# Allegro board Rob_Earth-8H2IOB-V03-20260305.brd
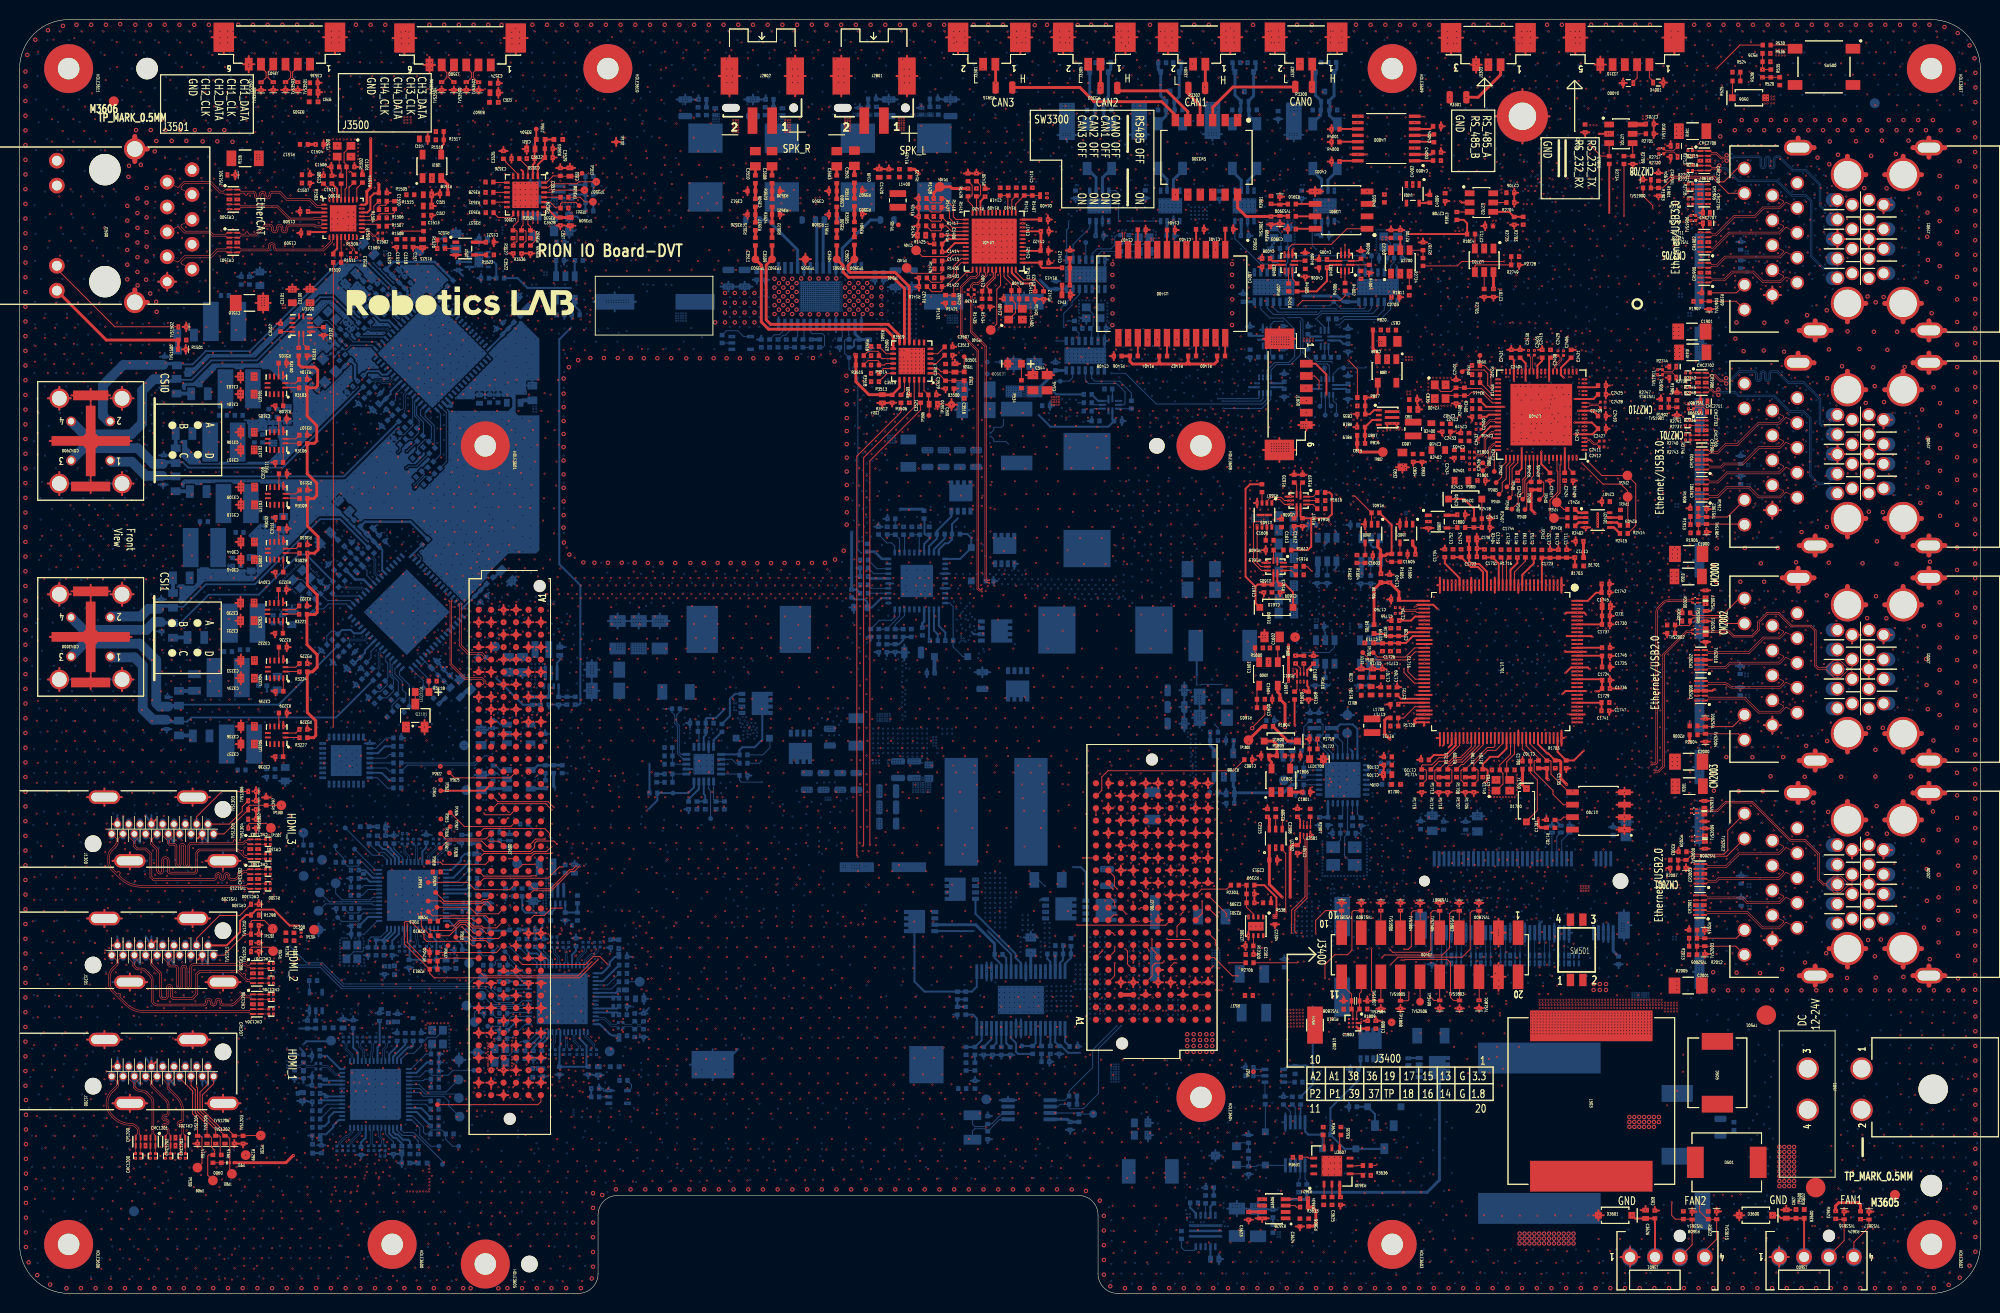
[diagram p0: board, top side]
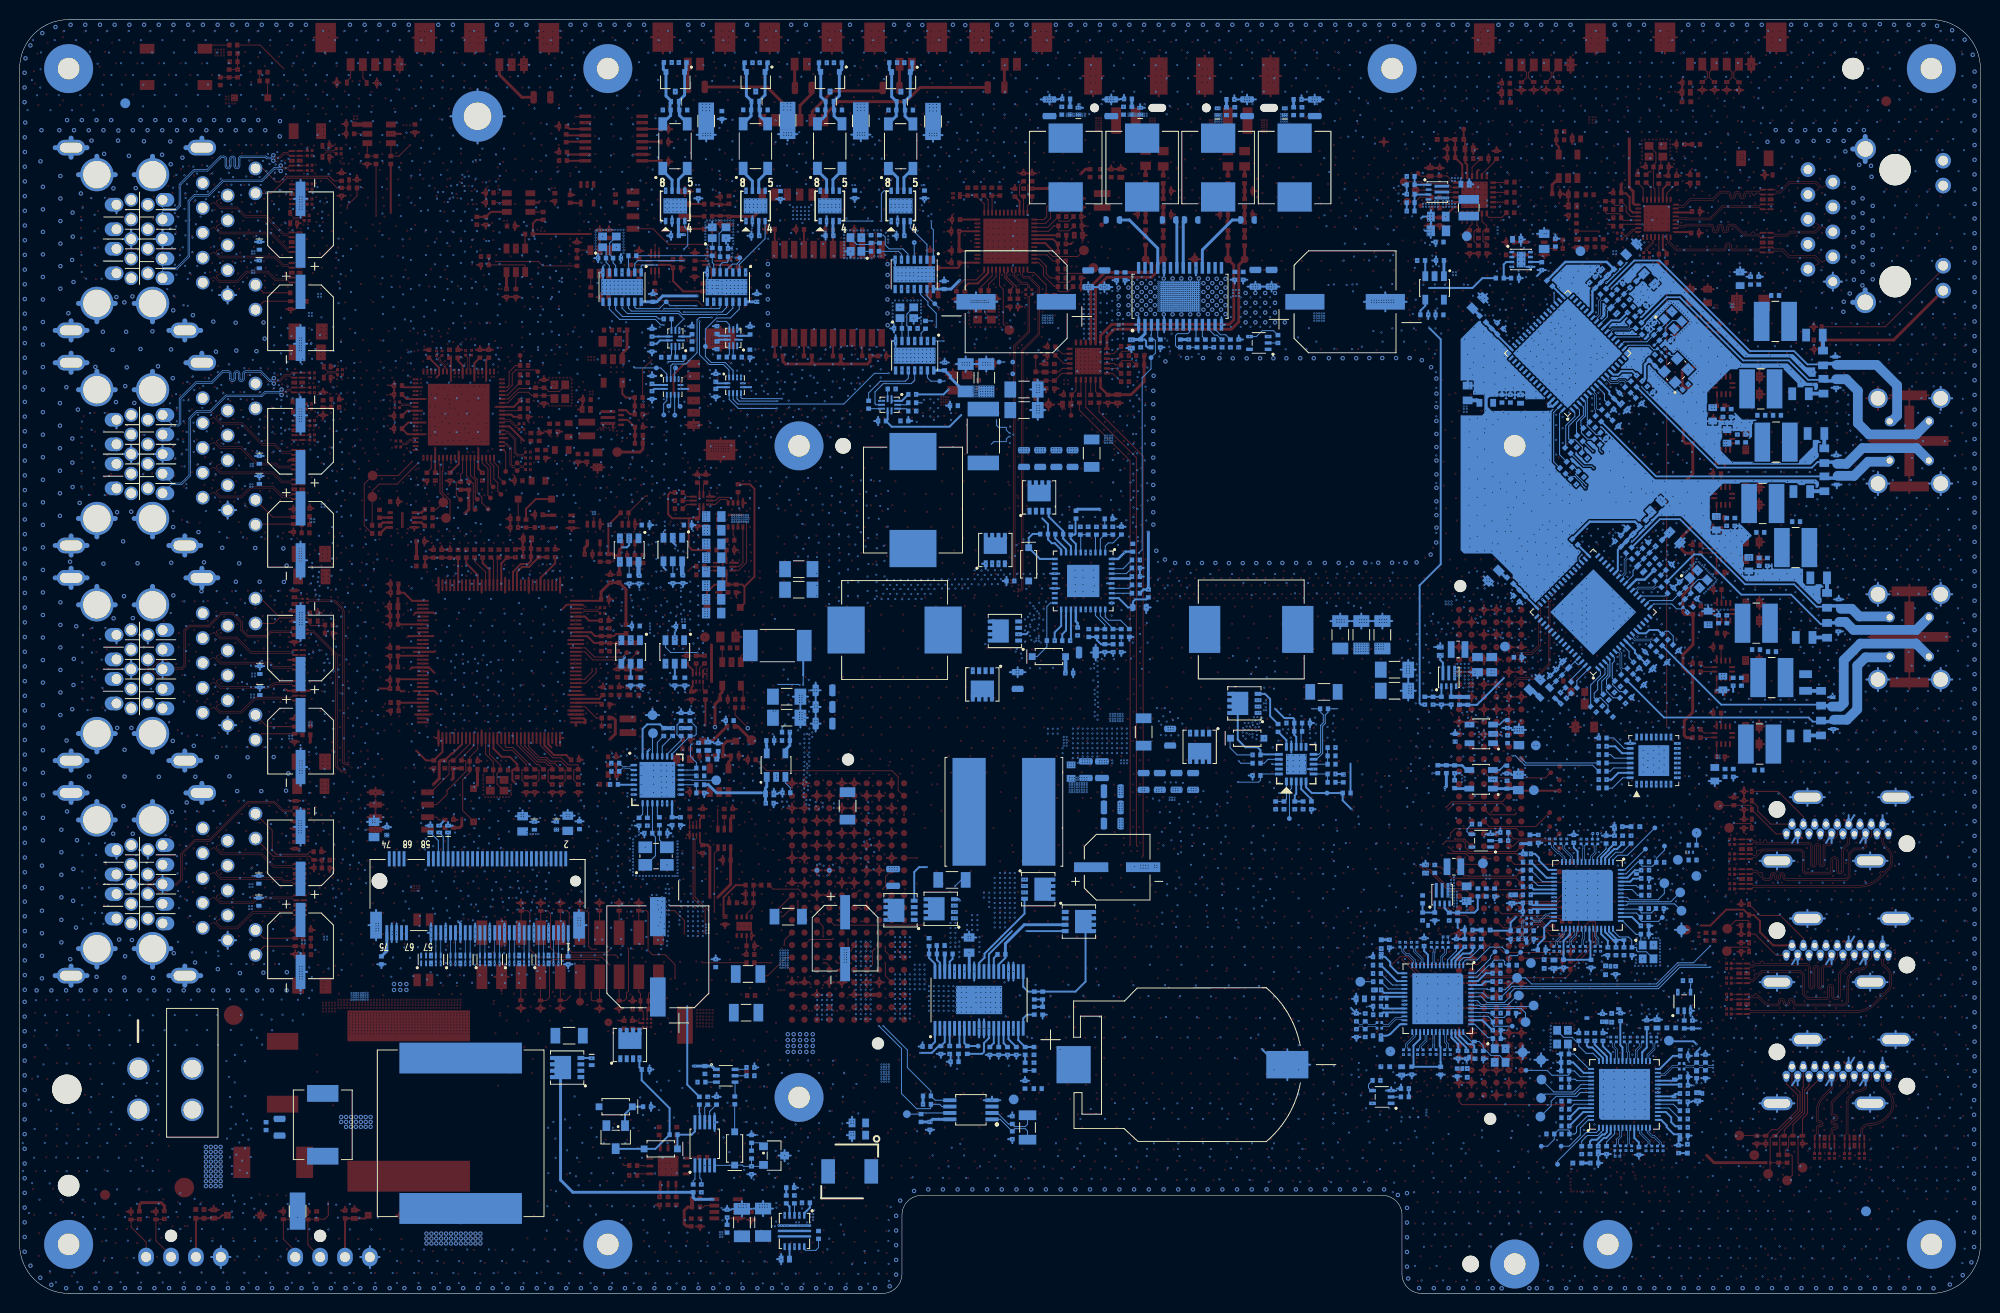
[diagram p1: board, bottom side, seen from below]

Outline 200 x 130 mm; copper layers: TOP, L2, L3, L4, L5, L6, L7, BOTTOM. Coordinates in mm from the lower left corner of the outline.
Outline path: 0,125 arc(1.46,128.54) 5,130 195,130 arc(198.54,128.54) 200,125 200,5 arc(198.54,1.46) 195,0 112,0 arc(110.59,0.59) 110,2 110,8 arc(109.41,9.41) 108,10 61,10 arc(59.59,9.41) 59,8 59,2 arc(58.41,0.59) 57,0 5,0 arc(1.46,1.46) 0,5 0,125

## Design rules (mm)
constraint set DEFAULT: min track width 0.1, pair gap 0.1
net group 8211_1_SGMII_CLK_: nets 8211_1_SGMII_CLK_M 8211_1_SGMII_CLK_P
net group CAN_MCLK1: nets CAN_MCLK1 N33124752
net group CAN_MCLK2: nets CAN_MCLK2 N33124961
net group CHANNEL1_IN: nets CHANNEL1_INM CHANNEL1_INP
net group CHANNEL2_IN: nets CHANNEL2_INM CHANNEL2_INP
net group CHANNEL3_IN: nets CHANNEL3_INM CHANNEL3_INP
net group CHANNEL4_IN: nets CHANNEL4_INM CHANNEL4_INP
net group DES0_SIOA_: nets DES0_SIOA_M DES0_SIOA_P
net group DES0_SIOB_: nets DES0_SIOB_M DES0_SIOB_P
net group DES0_SIOC_: nets DES0_SIOC_M DES0_SIOC_P
net group DES0_SIOD_: nets DES0_SIOD_M DES0_SIOD_P
net group DES1_SIOA_: nets DES1_SIOA_M DES1_SIOA_P
net group DES1_SIOB_: nets DES1_SIOB_M DES1_SIOB_P
net group DES1_SIOC_: nets DES1_SIOC_M DES1_SIOC_P
net group DES1_SIOD_: nets DES1_SIOD_M DES1_SIOD_P
net group DIFFPAIR10: nets PCIE1_TX0_M PCIE1_TX0_P
net group DIFFPAIR11: nets PCIE1_RX0_M PCIE1_RX0_P
net group DIFFPAIR14: nets PCIE1_REFCLK_M PCIE1_REFCLK_P
net group DP1: nets USB2_HUB_DM4 USB2_HUB_DP4
net group DP3: nets PCIE1_TX1_M PCIE1_TX1_P
net group DP4: nets PCIE1_RX1_M PCIE1_RX1_P
net group DP5: nets PCIE1_TX2_M PCIE1_TX2_P
net group DP6: nets PCIE1_RX2_M PCIE1_RX2_P
net group DP7: nets PCIE1_TX3_M PCIE1_TX3_P
net group DP8: nets PCIE1_RX3_M PCIE1_RX3_P
net group DP9: nets N30751825 N30751859
net group DP10: nets N30751883 N30751917
net group DP11: nets N30751975 N30752009
net group DP12: nets N30752033 N30752067
net group DP13: nets N30751690 N30751718
net group DP14: nets HSIN_C HSIP_C
net group DP16: nets N30797296 N30797329
net group DP22: nets N29328245 N29328252
net group DP23: nets N29318624 N29318651
net group DP25: nets N29318885 N29318891
net group DP26: nets N29318627 N29318675
net group DP28: nets N30797353 N30797387
net group DP29: nets HUB_USB2_DM_CON HUB_USB2_DP_CON
net group DP37: nets HUB_USB1_DM_CON HUB_USB1_DP_CON
net group DP40: nets HUB_USB3_DM_CON HUB_USB3_DP_CON
net group DP43: nets HUB_USB4_DM_CON HUB_USB4_DP_CON
net group DP44: nets HUB_USB3_RX_M HUB_USB3_RX_P
net group DP45: nets N30797440 N30797473
net group DP46: nets N30797491 N30797525
net group DP47: nets HUB_USB4_TX_M HUB_USB4_TX_P
net group DP48: nets HUB_USB4_RX_M HUB_USB4_RX_P
net group DP49: nets N30793801 N30793834
net group DP50: nets N30793858 N30793892
net group DP51: nets N30793945 N30793978
net group DP52: nets N30793996 N30794030
net group DP53: nets N30797523 N30797553
net group DP54: nets N30564853 N30564873
net group DP57: nets N30797438 N30797471
net group DP58: nets N30797385 N30797405
net group DP59: nets N30797294 N30797327
net group DP60: nets N30797137 N30797160
net group DP61: nets N30794028 N30794058
net group DP62: nets N30793943 N30793976
net group DP63: nets N30793890 N30793910
net group DP64: nets N30793799 N30793832
net group DP65: nets N30751823 N30751857
net group DP66: nets N30751915 N30751941
net group DP67: nets N30751973 N30752007
net group DP68: nets N30752065 N30752096
net group DP74: nets N31105694 N31105696
net group DP76: nets N30852150 N30852169
net group DP77: nets N30793642 N30793665
net group HSO_C: nets HSON_C HSOP_C
net group HUB_P2_USB_HS_: nets USB1_HS_D_M USB1_HS_D_P
net group HUB_USB1_D: nets HUB_USB1_DM HUB_USB1_DP
net group HUB_USB1_RX_: nets HUB_USB1_RX_M HUB_USB1_RX_P
net group HUB_USB1_TX_: nets HUB_USB1_TX_M HUB_USB1_TX_P
net group HUB_USB2_D: nets HUB_USB2_DM HUB_USB2_DP
net group HUB_USB2_RX_: nets HUB_USB2_RX_M HUB_USB2_RX_P
net group HUB_USB2_TX_: nets HUB_USB2_TX_M HUB_USB2_TX_P
net group HUB_USB3_D: nets HUB_USB3_DM HUB_USB3_DP
net group HUB_USB3_TX_: nets HUB_USB3_TX_M HUB_USB3_TX_P
net group HUB_USB4_D: nets HUB_USB4_DM HUB_USB4_DP
net group HUBPCIE14_REFCLK: nets HUBPCIE14_REFCLKN HUBPCIE14_REFCLKP
net group HUBPCIE14_RX_: nets HUBPCIE14_RX_N HUBPCIE14_RX_P
net group HUBPCIE14_TX_: nets HUBPCIE14_TX_N HUBPCIE14_TX_P
net group P1_MDI: nets P1_MDI_AN P1_MDI_AP
net group P1_MDI_B: nets P1_MDI_BN P1_MDI_BP
net group P1_MDI_C: nets P1_MDI_CN P1_MDI_CP
net group P1_MDI_D: nets P1_MDI_DN P1_MDI_DP
net group P2_MDI: nets P2_MDI_AN P2_MDI_AP
net group P2_MDI_B: nets P2_MDI_BN P2_MDI_BP
net group P2_MDI_C: nets P2_MDI_CN P2_MDI_CP
net group P2_MDI_D: nets P2_MDI_DN P2_MDI_DP
net group SAIL_CAN_0_: nets SAIL_CAN_0_M SAIL_CAN_0_P
net group SAIL_CAN_1_: nets SAIL_CAN_1_M SAIL_CAN_1_P
net group SGMII1_RX_: nets SGMII1_RX_M SGMII1_RX_P
net group SGMII1_TX_: nets SGMII1_TX_M SGMII1_TX_P
net group SSRX0: nets SSRX0+ SSRX0-
net group SSTX0: nets SSTX0+ SSTX0-
net group SSTX1: nets SSTX1+ SSTX1-
net group SSTX2: nets SSTX2+ SSTX2-
net group SSTX3: nets SSTX3+ SSTX3-
net group SSTX4: nets SSTX4+ SSTX4-
net group USB1_SS_RX_: nets USB1_SS_RX_M USB1_SS_RX_P
net group USB1_SS_TX_: nets USB1_SS_TX_M USB1_SS_TX_P
net group USB2_HS_D_: nets USB2_HUB_DM1 USB2_HUB_DP1
net group USB2_HUB2_D1: nets USB2_HUB2_DM1 USB2_HUB2_DP1
net group USB2_HUB2_D2: nets USB2_HUB2_DM2 USB2_HUB2_DP2
net group USB2_HUB2_D3: nets USB2_HUB2_DM3 USB2_HUB2_DP3
net group USB2_HUB2_D4: nets USB2_HUB2_DM4 USB2_HUB2_DP4
net group USBDP0: nets USBDP0+ USBDP0-
net group 8211: nets 8211_TRXN0 8211_TRXN1 8211_TRXN2 8211_TRXN3 8211_TRXP0 8211_TRXP1 8211_TRXP2 8211_TRXP3
net group CSI0: nets CSI0_A0_CLK_M CSI0_A1_LN1_P CSI0_A2_LN2_M CSI0_B0_LN0_P CSI0_B1_LN1_M CSI0_B2_LN3_P CSI0_C0_LN0_M CSI0_C1_LN2_P CSI0_C2_LN3_M CSI0_NC_CLK_P
net group CSI1: nets CSI1_A0_CLK_M CSI1_A1_LN1_P CSI1_A2_LN2_M CSI1_B0_LN0_P CSI1_B1_LN1_M CSI1_B2_LN3_P CSI1_C0_LN0_M CSI1_C1_LN2_P CSI1_C2_LN3_M CSI1_NC_CLK_P
net group EDP1: nets EDP1_AUX_M EDP1_AUX_P EDP1_LN0_M EDP1_LN0_P EDP1_LN1_M EDP1_LN1_P EDP1_LN2_M EDP1_LN2_P EDP1_LN3_M EDP1_LN3_P
net group EDP2: nets EDP2_AUX_M EDP2_AUX_P EDP2_LN0_M EDP2_LN0_P EDP2_LN1_M EDP2_LN1_P EDP2_LN2_M EDP2_LN2_P EDP2_LN3_M EDP2_LN3_P
net group EDP3: nets EDP3_AUX_M EDP3_AUX_P EDP3_LN0_M EDP3_LN0_P EDP3_LN1_M EDP3_LN1_P EDP3_LN2_M EDP3_LN2_P EDP3_LN3_M EDP3_LN3_P
net group HDIM1: nets HDMI1_CLK_N HDMI1_CLK_P HDMI1_TX0_N HDMI1_TX0_P HDMI1_TX1_N HDMI1_TX1_P HDMI1_TX2_N HDMI1_TX2_P
net group HDIM3: nets HDMI3_CLK_N_CONN HDMI3_CLK_P_CONN HDMI3_TX0_N_CONN HDMI3_TX0_P_CONN HDMI3_TX1_P_CONN HDMI3_TX2_N_CONN HDMI3_TX2_P_CONN
net group HDMI2: nets HDMI2_CLK_N HDMI2_CLK_N_CONN HDMI2_CLK_P HDMI2_CLK_P_CONN HDMI2_TX0_N HDMI2_TX0_N_CONN HDMI2_TX0_P HDMI2_TX0_P_CONN HDMI2_TX1_N HDMI2_TX1_N_CONN HDMI2_TX1_P HDMI2_TX1_P_CONN HDMI2_TX2_N HDMI2_TX2_N_CONN HDMI2_TX2_P HDMI2_TX2_P_CONN
net group HDMI3: nets HDMI3_CLK_N HDMI3_CLK_P HDMI3_TX0_N HDMI3_TX0_P HDMI3_TX1_N HDMI3_TX1_P HDMI3_TX2_N HDMI3_TX2_P
net group HUB_USB1_CON: nets HUB_USB1_RX_M_CON HUB_USB1_RX_P_CON HUB_USB1_TX_M_CON HUB_USB1_TX_P_CON
net group HUB_USB2: nets HUB_USB2_RX_M_CON HUB_USB2_RX_P_CON HUB_USB2_TX_M_CON HUB_USB2_TX_P_CON
net group HUB_USB3_CON: nets HUB_USB3_RX_M_CON HUB_USB3_RX_P_CON HUB_USB3_TX_M_CON HUB_USB3_TX_P_CON
net group HUB_USB4: nets HUB_USB4_RX_M_CON HUB_USB4_RX_P_CON HUB_USB4_TX_M_CON HUB_USB4_TX_P_CON
net group P0MDI: nets P0MDIAN P0MDIAP P0MDIBN P0MDIBP P0MDICN P0MDICP P0MDIDN P0MDIDP
net group P3_MDI: nets P3_MDI_AN P3_MDI_AP P3_MDI_BN P3_MDI_BP P3_MDI_CN P3_MDI_CP P3_MDI_DN P3_MDI_DP
net group P4_MDI: nets P4_MDI_AN P4_MDI_AP P4_MDI_BN P4_MDI_BP P4_MDI_CN P4_MDI_CP P4_MDI_DN P4_MDI_DP
net group SGMII0: nets SGMII0_RX_M SGMII0_RX_P SGMII0_TX_M SGMII0_TX_P
nets with their own width: nets GND

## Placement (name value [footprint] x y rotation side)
B900  120R/1.3A  [FB0402H0_5]  31.53 27.1 0 bottom
B901  120R/1.3A  [FB0402H0_5]  41.12 13.3 180 bottom
B902  120R/1.3A  [FB0402H0_5]  37.61 28.13 270 bottom
B903  120R/1.3A  [FB0402H0_5]  29.88 14.77 270 bottom
B1000  120R/1.3A  [FB0402H0_5]  60.7 23.14 180 bottom
B1001  120R/1.3A  [FB0402H0_5]  50.46 37.09 0 bottom
B1002  120R/1.3A  [FB0402H0_5]  52.34 22.5 90 bottom
B1003  120R/1.3A  [FB0402H0_5]  61.12 35.64 90 bottom
B1100  120R/1.3A  [FB0402H0_5]  44.5 33.62 90 bottom
B1101  120R/1.3A  [FB0402H0_5]  35.19 47.64 0 bottom
B1102  120R/1.3A  [FB0402H0_5]  38.24 32.98 90 bottom
B1103  120R/1.3A  [FB0402H0_5]  45.95 46.35 90 bottom
B1700  120R/1.3A  [FB0402H0_5]  140.4 51.95 0 top
B1701  120R/1.3A  [FB0402H0_5]  159.08 75.1 0 top
B1702  120R/1.3A  [FB0402H0_5]  137.66 66.39 0 top
B1703  120R/1.3A  [FB0402H0_5]  159.09 74.24 0 top
B1704  120R/1.3A  [FB0402H0_5]  136.85 61.5 90 top
B1705  120R/1.3A  [FB0402H0_5]  138.15 67.8 270 top
B1706  120R/1.3A  [FB0402H0_5]  138.85 73 270 top
B2400  120R/3.0A  [FB0603H0_95]  144 88.12 90 top
B2401  120R/3.0A  [FB0603H0_95]  147.08 82.94 0 top
B2402  120R/3.0A  [FB0603H0_95]  144.7 86.07 0 top
B2500  120R/1.3A  [FB0402H0_5]  129.35 54.52 180 bottom
B2900  120R/1.3A  [FB0402H0_5]  35.41 102.97 315 bottom
B2901  120R/1.3A  [FB0402H0_5]  37.04 104.84 135 bottom
B2902  120R/3.0A  [FB0603H0_95]  50.4 90.89 0 bottom
B2903  120R/1.3A  [FB0402H0_5]  50.75 99.43 225 bottom
B3000  120R/1.3A  [FB0402H0_5]  32.8 76.56 315 bottom
B3001  120R/3.0A  [FB0603H0_95]  44.44 61.33 315 bottom
B3002  120R/1.3A  [FB0402H0_5]  34.44 78.59 135 bottom
B3003  120R/1.3A  [FB0402H0_5]  47.96 72.74 225 bottom
B3500  120R/1.3A  [FB0402H0_5]  96.35 91.8 90 top
B3501  NC 120R/1.3A  [FB0402H0_5]  96.35 93.6 90 top
B3502  120R/1.3A  [FB0402H0_5]  48.38 121.56 180 top
B3503  120R/1.3A  [FB0402H0_5]  54.95 117.77 180 top
B3504  NC 120R/1.3A  [FB0402H0_5]  53.15 117.77 180 top
B3505  120R/1.3A  [FB0402H0_5]  29.99 121.61 180 top
B3600  120R/1.3A  [FB0402H0_5]  182.03 8.11 90 top
B3602  NC 120R/1.3A  [FB0402H0_5]  181.19 8.11 90 top
C500  100nF/50V_2  [0402]  174.86 17.07 270 bottom
C501  100nF/50V_2  [0402]  129 33.7 90 bottom
C502  10uF/50V_5  [SC0805H1_45]  173.49 16.96 270 bottom
C503  470nF/16V_2  [0402]  86.14 73.16 0 bottom
C504  2.2uF/10V_2  [0402]  91.01 77.84 270 bottom
C505  2.2uF/10V_2  [0402]  92.94 63.31 0 bottom
C506  100nF/50V_2  [0402]  95.51 77.49 0 bottom
C507  2.2uF/10V_2  [0402]  98.94 72.71 180 bottom
C508  100nF/50V_2  [0402]  94.82 66.62 180 bottom
C509  100nF/16V_2  [0402]  104.7 90.6 180 bottom
C510  100uF/6.3V_6  [SC1206H1_8]  97.55 90.15 180 bottom
C511  100uF/6.3V_6  [SC1206H1_8]  97.55 92.25 180 bottom
C512  100uF/6.3V_6  [SC1206H1_8]  101.4 93.45 90 bottom
C513  100uF/6.3V_6  [SC1206H1_8]  103.5 93.45 90 bottom
C514  47uF/25V_6  [SC1206H1_8]  120.53 71.81 180 bottom
C515  47uF/25V_6  [SC1206H1_8]  120.53 73.91 180 bottom
C516  47uF/25V_6  [SC1206H1_8]  121.76 58.75 180 bottom
C517  47uF/25V_6  [SC1206H1_8]  121.76 60.9 180 bottom
C518  100nF/16V_2  [0402]  127.57 58.46 180 bottom
C519  NC 39pF/50V_2  [0402]  88.48 67.4 90 bottom
C520  100nF/16V_2  [0402]  86.81 67.4 90 bottom
C521  6.8nF/50V_2  [0402]  87.63 65.85 90 bottom
C522  220nF/50V_3  [SC0603]  85.76 70.01 0 bottom
C523  10nF/50V_2  [0402]  86.14 74.86 0 bottom
C524  22uF/10V_3  [SC0603DE-H1_1]  129.21 69.43 0 bottom
C525  22uF/10V_3  [SC0603DE-H1_1]  129.21 70.83 0 bottom
C526  22uF/10V_3  [SC0603DE-H1_1]  129.21 72.23 0 bottom
C527  22uF/10V_3  [SC0603DE-H1_1]  129.21 73.63 0 bottom
C528  10uF/50V_5  [SC0805H1_45]  91.09 65.41 180 bottom
C529  10uF/50V_5  [SC0805H1_45]  98.2 62.55 90 bottom
C530  10uF/50V_5  [SC0805H1_45]  117.95 58.15 0 bottom
C531  10uF/50V_5  [SC0805H1_45]  117.95 59.85 0 bottom
C532  10uF/50V_5  [SC0805H1_45]  117.95 61.55 0 bottom
C533  10uF/50V_5  [SC0805H1_45]  92.6 85.2 90 bottom
C534  10uF/50V_5  [SC0805H1_45]  97.55 85.2 90 bottom
C535  10uF/50V_5  [SC0805H1_45]  94.25 85.2 90 bottom
C536  10uF/50V_5  [SC0805H1_45]  95.9 85.2 90 bottom
C537  22uF/10V_3  [SC0603DE-H1_1]  129.19 75.08 0 bottom
C538  22uF/10V_3  [SC0603DE-H1_1]  129.19 76.48 0 bottom
C539  22uF/10V_3  [SC0603DE-H1_1]  129.19 77.88 0 bottom
C540  22uF/10V_3  [SC0603DE-H1_1]  129.19 79.28 0 bottom
C541  100nF/50V_2  [0402]  128.92 19.67 270 bottom
C542  100nF/50V_2  [0402]  130.47 10.72 90 bottom
C543  1uF/10V_2  [0402]  125.45 23.06 180 bottom
C544  22uF/10V_3  [SC0603DE-H1_1]  103.35 92.95 90 top
C545  22uF/10V_3  [SC0603DE-H1_1]  104.8 92.95 90 top
C546  1uF/10V_2  [0402]  130.1 22.8 270 bottom
C547  100nF/50V_2  [0402]  125.35 12.57 90 bottom
C548  2.2nF/50V_2  [0402]  136.15 22.85 180 bottom
C549  6.8pF/50V_2  [0402]  88.49 77.84 270 bottom
C550  100nF/16V_2  [0402]  87.61 77.84 270 bottom
C551  3.9nF/50V_2  [0402]  88.92 79.05 0 bottom
C608  10uF/50V_5  [SC0805H1_45]  85.35 52.25 270 bottom
C609  10uF/50V_5  [SC0805H1_45]  82.65 56.77 90 bottom
C610  10uF/50V_5  [SC0805H1_45]  80.3 52.25 270 bottom
C611  10uF/50V_5  [SC0805H1_45]  82 52.25 270 bottom
C612  10uF/50V_5  [SC0805H1_45]  83.7 52.25 270 bottom
C613  100nF/50V_2  [0402]  73.84 54.96 0 bottom
C614  2.2uF/10V_2  [0402]  70.39 58.21 0 bottom
C615  NC 68pF/50V_2  [0402]  66.19 54.86 180 bottom
C616  47uF/25V_6  [SC1206H1_8]  61 67.22 90 bottom
C617  47uF/25V_6  [SC1206H1_8]  59.76 61.5 180 bottom
C618  47uF/25V_6  [SC1206H1_8]  65.3 67.22 90 bottom
C619  47uF/25V_6  [SC1206H1_8]  63.15 67.22 90 bottom
C620  47uF/25V_6  [SC1206H1_8]  59.76 63.65 180 bottom
C621  22nF/50V_2  [0402]  66.95 59.67 180 bottom
C622  10nF/50V_2  [0402]  64.99 52.56 90 bottom
C623  22pF/50V_2  [0402]  66.19 53.01 180 bottom
C700  22uF/35V_5  [SC0805]  110.9 42.45 90 bottom
C701  120pF/50V_2  [0402]  106.83 34.65 0 bottom
C702  22uF/35V_5  [SC0805]  88.55 51.25 180 bottom
C703  100nF/50V_2  [0402]  106.03 24.85 270 bottom
C704  22uF/35V_5  [SC0805]  89.6 53.45 90 bottom
C705  22uF/10V_3  [SC0603DE-H1_1]  103.15 35.55 90 bottom
C706  100nF/16V_2  [0402]  107.5 25.2 0 bottom
C707  100nF/50V_2  [0402]  105.23 34.65 180 bottom
C708  100nF/50V_2  [0402]  99.85 34.6 0 bottom
C709  6.8nF/50V_2  [0402]  97.43 24.75 270 bottom
C710  NC 68pF/50V_2  [0402]  96.5 30.4 90 bottom
C711  6.8nF/50V_2  [0402]  104.63 23.65 0 bottom
C712  82pF/50V_2  [0402]  96.53 24.75 270 bottom
C713  6.8nF/50V_2  [0402]  98.33 24.75 270 bottom
C800  100nF/16V_2  [0402]  118.51 5.97 270 bottom
C801  10uF/25V_3  [SC0603A-H0_9]  114.4 16.15 0 bottom
C802  10uF/25V_3  [SC0603A-H0_9]  114.4 17.4 0 bottom
C803  47uF/25V_6  [SC1206H1_8]  124.17 7.26 90 bottom
C804  47uF/25V_6  [SC1206H1_8]  126.32 7.23 90 bottom
C805  4.7uF/16V_2  [0402W]  121.9 3.5 180 bottom
C806  6.8nF/50V_2  [0402]  121.4 10.79 0 bottom
C807  NC 6.8pF/50V_2  [0402]  58.11 111.32 180 bottom
C808  4.7uF/6.3V_2  [0402W]  56.6 43.32 90 bottom
C809  100nF/16V_2  [0402]  55.65 43.32 90 bottom
C810  1uF/10V_2  [0402]  50.4 40.92 270 bottom
C811  100pF/50V_2  [0402]  49.55 40.92 270 bottom
C812  NC 6.8pF/50V_2  [0402]  51.25 40.92 270 bottom
C813  47uF/6.3V_3  [SC0603BC-H1_0]  52.4 40.79 270 bottom
C814  NC 100nF/50V_2  [0402]  55.65 38.47 270 bottom
C815  NC 6.8pF/50V_2  [0402]  136.84 86.75 0 top
C820  2.2uF/10V_2  [0402]  53.58 56.71 90 bottom
C821  100nF/16V_2  [0402]  48.23 56.55 90 bottom
C822  22uF/10V_3  [SC0603DE-H1_1]  47.08 56.73 90 bottom
C823  2.2uF/10V_2  [0402]  53.63 51.97 90 bottom
C824  100nF/16V_2  [0402]  48.28 51.92 90 bottom
C825  22uF/10V_3  [SC0603DE-H1_1]  47.13 52.14 90 bottom
C826  10uF/10V_2  [0402W]  52.56 113.2 180 bottom
C827  47uF/6.3V_3  [SC0603BC-H1_0]  55.29 109.9 0 bottom
C828  NC 22uF/10V_3  [SC0603DE-H1_1]  55.29 108.45 0 bottom
C829  100nF/16V_2  [0402]  55.16 107.3 0 bottom
C830  NC 100nF/50V_2  [0402]  58.11 113.15 0 bottom
C831  10uF/10V_2  [0402W]  142.2 90.22 0 top
C832  47uF/6.3V_3  [SC0603BC-H1_0]  141.05 85.07 270 top
C833  1uF/10V_2  [0402]  142.15 85.27 270 top
C834  100nF/16V_2  [0402]  143.05 85.27 270 top
C835  NC 100nF/50V_2  [0402]  136.85 90.58 180 top
C836  2.2uF/10V_2  [0402]  142.15 91.22 0 top
C837  100nF/16V_2  [0402]  139.99 98.31 180 top
C838  22uF/10V_3  [SC0603DE-H1_1]  139.76 97.16 180 top
C840  NC 100nF/50V_2  [0402]  53.63 53.49 270 bottom
C900  100nF/10V_1  [0201]  30.47 22.9 0 bottom
C901  100nF/10V_1  [0201]  30.47 23.47 0 bottom
C902  12pF/50V_2  [0402]  42.37 24.43 0 bottom
C903  12pF/50V_2  [0402]  40.96 26.17 90 bottom
C904  0.5pF/50V_1  [0201]  37.02 14.01 0 bottom
C905  1uF/10V_2  [0402]  42.36 21.87 0 bottom
C906  10uF/10V_2  [0402W]  32.99 27.51 90 bottom
C907  100nF/16V_2  [0402]  34.03 27.48 90 bottom
C908  100nF/16V_2  [0402]  36.7 28.2 90 bottom
C909  100nF/16V_2  [0402]  40.15 26.18 90 bottom
C910  100nF/16V_2  [0402]  30.23 22.1 180 bottom
C911  1uF/10V_2  [0402]  39.38 13.3 180 bottom
C912  100nF/16V_2  [0402]  39.82 14.62 270 bottom
C913  10uF/10V_2  [0402W]  28.85 20.07 270 bottom
C914  100nF/16V_2  [0402]  30.25 16.95 180 bottom
C915  100nF/16V_2  [0402]  30.25 20.4 180 bottom
C916  100nF/16V_2  [0402]  42.33 17.09 0 bottom
C917  100nF/16V_2  [0402]  42.36 23.58 0 bottom
C918  100nF/16V_2  [0402]  30.25 19.55 180 bottom
C919  100nF/16V_2  [0402]  42.33 17.93 0 bottom
C920  100nF/16V_2  [0402]  30.22 24.24 180 bottom
C921  100nF/16V_2  [0402]  30.25 16.1 180 bottom
C922  1uF/10V_2  [0402]  38.55 28.12 90 bottom
C923  100nF/16V_2  [0402]  38.5 26.17 90 bottom
C924  100nF/16V_2  [0402]  39.33 26.18 90 bottom
C925  100nF/16V_2  [0402]  30.23 21.23 180 bottom
C926  4.7uF/6.3V_2  [0402]  30.78 14.72 90 bottom
C927  100nF/16V_2  [0402]  34.83 14.55 270 bottom
C928  100nF/16V_2  [0402]  38.98 14.62 270 bottom
C1000  100nF/10V_1  [0201]  61.3 27.64 180 bottom
C1001  100nF/10V_1  [0201]  61.3 27.07 180 bottom
C1002  0.5pF/50V_1  [0201]  54.56 36.38 180 bottom
C1003  12pF/50V_2  [0402]  49.32 26.01 180 bottom
C1004  12pF/50V_2  [0402]  50.7 24.35 270 bottom
C1005  1uF/10V_2  [0402]  47.77 28.6 180 bottom
C1006  10uF/10V_2  [0402W]  59.03 22.71 270 bottom
C1007  100nF/16V_2  [0402]  58 22.74 270 bottom
C1008  100nF/16V_2  [0402]  55.05 22.73 270 bottom
C1009  100nF/16V_2  [0402]  51.55 24.35 270 bottom
C1010  100nF/16V_2  [0402]  61.54 28.44 0 bottom
C1011  1uF/10V_2  [0402]  52.2 37.09 0 bottom
C1012  100nF/16V_2  [0402]  51.76 35.77 90 bottom
C1013  10uF/10V_2  [0402W]  63.25 30.07 0 bottom
C1014  100nF/16V_2  [0402]  61.53 30.13 0 bottom
C1015  100nF/16V_2  [0402]  49.36 32.68 180 bottom
C1016  100nF/16V_2  [0402]  49.33 26.86 180 bottom
C1017  100nF/16V_2  [0402]  61.55 33.5 0 bottom
C1018  100nF/16V_2  [0402]  61.52 30.97 0 bottom
C1019  100nF/16V_2  [0402]  49.36 31.83 180 bottom
C1020  100nF/16V_2  [0402]  61.55 26.3 0 bottom
C1021  100nF/16V_2  [0402]  61.55 34.35 0 bottom
C1022  1uF/10V_2  [0402]  53.36 22.55 270 bottom
C1023  100nF/16V_2  [0402]  53.27 24.37 270 bottom
C1024  100nF/16V_2  [0402]  52.4 24.35 270 bottom
C1025  100nF/16V_2  [0402]  61.54 29.3 0 bottom
C1026  4.7uF/6.3V_2  [0402]  60.29 35.69 270 bottom
C1027  100nF/16V_2  [0402]  56.74 35.85 90 bottom
C1028  100nF/16V_2  [0402]  52.6 35.77 90 bottom
C1100  100nF/10V_1  [0201]  46.03 38.29 180 bottom
C1101  100nF/10V_1  [0201]  46.03 37.72 180 bottom
C1102  0.5pF/50V_1  [0201]  39.29 46.93 180 bottom
C1103  12pF/50V_2  [0402]  34.23 36.66 180 bottom
C1104  12pF/50V_2  [0402]  35.54 34.91 270 bottom
C1105  1uF/10V_2  [0402]  32.7 39.28 180 bottom
C1106  10uF/10V_2  [0402W]  43.5 33.6 270 bottom
C1107  100nF/16V_2  [0402]  42.52 33.66 270 bottom
C1108  100nF/16V_2  [0402]  39.72 33.65 270 bottom
C1109  100nF/16V_2  [0402]  36.36 34.91 270 bottom
C1110  100nF/16V_2  [0402]  46.27 38.99 0 bottom
C1111  1uF/10V_2  [0402]  36.93 47.63 0 bottom
C1112  100nF/16V_2  [0402]  36.49 46.31 90 bottom
C1113  10uF/10V_2  [0402W]  47.79 40.25 270 bottom
C1114  100nF/16V_2  [0402]  46.25 44.02 0 bottom
C1115  100nF/16V_2  [0402]  46.26 40.68 0 bottom
C1116  100nF/16V_2  [0402]  34.2 43.2 180 bottom
C1117  100nF/16V_2  [0402]  34.24 37.52 180 bottom
C1118  100nF/16V_2  [0402]  34.2 42.35 180 bottom
C1119  100nF/16V_2  [0402]  46.25 41.51 0 bottom
C1120  100nF/16V_2  [0402]  44.75 35.07 180 bottom
C1121  100nF/16V_2  [0402]  46.25 44.86 0 bottom
C1122  1uF/10V_2  [0402]  37.2 32.98 270 bottom
C1123  100nF/16V_2  [0402]  38 34.92 270 bottom
C1124  100nF/16V_2  [0402]  37.17 34.91 270 bottom
C1125  100nF/16V_2  [0402]  46.27 39.85 0 bottom
C1126  4.7uF/6.3V_2  [0402]  45.1 46.39 270 bottom
C1127  100nF/16V_2  [0402]  41.47 46.39 90 bottom
C1128  100nF/16V_2  [0402]  37.33 46.32 90 bottom
C1400  100nF/10V_1  [0201]  97.37 102.19 90 top
C1401  100nF/16V_2  [0402]  123.38 108.61 180 top
C1402  100nF/10V_1  [0201]  96.75 102.18 90 top
C1403  100nF/16V_2  [0402]  120.39 108.59 180 top
C1404  100nF/16V_2  [0402]  117.43 108.52 180 top
C1405  10uF/10V_2  [0402W]  92 107.99 180 top
C1406  100nF/16V_2  [0402]  93.64 107.99 0 top
C1407  100nF/16V_2  [0402]  114.46 108.55 180 top
C1408  100nF/50V_2  [0402]  112 95.66 180 top
C1409  12pF/50V_2  [0402]  100.77 101.5 180 top
C1410  NC 1uF/10V_2  [0402]  102.47 112.45 90 top
C1411  12pF/50V_2  [0402]  102.36 101.5 0 top
C1412  1uF/10V_2  [0402]  107.13 106.04 90 top
C1413  10uF/10V_2  [0402W]  106.74 101.9 0 top
C1414  100nF/16V_2  [0402]  93.69 107.1 0 top
C1415  100nF/16V_2  [0402]  93.69 106.3 0 top
C1416  100nF/16V_2  [0402]  104.55 105.18 180 top
C1417  100nF/16V_2  [0402]  104.49 109.59 180 top
C1418  100nF/16V_2  [0402]  98.48 112.33 270 top
C1419  10uF/10V_2  [0402W]  87.68 114.33 90 top
C1420  100nF/16V_2  [0402]  88.66 114.32 270 top
C1421  100nF/16V_2  [0402]  104.53 106.42 180 top
C1422  100nF/16V_2  [0402]  104.57 108.39 180 top
C1423  100nF/16V_2  [0402]  103.58 101.86 90 top
C1500  12pF/50V_2  [0402]  32.2 114.97 180 top
C1501  12pF/50V_2  [0402]  33.75 114.97 0 top
C1502  100nF/10V_1  [0201]  36.8 108.22 0 top
C1503  100nF/10V_1  [0201]  36.8 107.62 0 top
C1504  100nF/16V_2  [0402]  30.6 117.27 0 top
C1506  100nF/16V_2  [0402]  29.2 114.17 0 top
C1507  100nF/16V_2  [0402]  29.2 113.32 0 top
C1508  100nF/16V_2  [0402]  29.02 110.42 180 top
C1509  100nF/16V_2  [0402]  29.11 108.22 180 top
C1510  100nF/16V_2  [0402]  37.05 112.32 0 top
C1511  100nF/16V_2  [0402]  31.85 113.67 90 top
C1512  4.7uF/6.3V_2  [0402W]  41.6 110.98 0 top
C1513  100nF/16V_2  [0402]  41.6 110.03 0 top
C1514  4.7uF/6.3V_2  [0402W]  41.2 117.83 0 top
C1515  4.7uF/6.3V_2  [0402W]  41.6 112.13 0 top
C1516  1nF/2KV_6  [SC1206]  23.44 101.09 180 top
C1517  4.7uF/6.3V_2  [0402W]  41.1 107.16 270 top
C1518  100nF/16V_2  [0402]  40.14 107.18 270 top
C1519  100nF/16V_2  [0402]  39.31 107.19 270 top
C1520  100nF/16V_2  [0402]  38.47 107.18 270 top
C1521  1uF/10V_2  [0402]  47.97 107.29 180 top
C1600  2.2uF/10V_2  [0402]  128.17 60.64 180 top
C1601  100nF/16V_2  [0402]  127.93 65.88 180 top
C1602  22uF/10V_3  [SC0603DE-H1_1]  127.75 67 180 top
C1603  100nF/16V_2  [0402]  138.43 75.29 0 top
C1604  NC 100nF/50V_2  [0402]  126.61 60.64 0 top
C1605  1uF/10V_2  [0402]  141.97 75.43 0 top
C1606  100nF/16V_2  [0402]  128.72 78.61 90 top
C1607  1uF/10V_2  [0402]  131.97 64.67 270 top
C1608  100nF/16V_2  [0402]  131.47 61.02 90 top
C1609  1uF/10V_2  [0402]  128.57 71.95 270 top
C1610  100nF/16V_2  [0402]  127.74 71.95 270 top
C1611  2.2uF/10V_2  [0402]  126.91 71.95 90 top
C1612  1uF/10V_2  [0402]  130.86 78.7 270 top
C1613  100nF/16V_2  [0402]  129.99 78.7 270 top
C1700  12pF/50V_2  [0402]  152.09 53.43 0 top
C1701  10nF/50V_2  [0402]  155.75 47.93 90 top
C1702  NC 1uF/10V_2  [0402]  153.69 54.33 180 top
C1703  12pF/50V_2  [0402]  150.58 53.43 180 top
C1704  10uF/10V_2  [0402W]  139.54 52.95 180 top
C1705  100nF/16V_2  [0402]  139.56 53.93 180 top
C1706  10nF/50V_2  [0402]  139.56 54.76 180 top
C1707  1uF/10V_2  [0402]  138.84 61.47 90 top
C1708  10uF/10V_2  [0402W]  137.85 61.5 90 top
C1709  10nF/50V_2  [0402]  139.67 61.47 90 top
C1710  10nF/50V_2  [0402]  156.1 75.48 90 top
C1711  1uF/10V_2  [0402]  156.96 75.49 90 top
C1712  10nF/50V_2  [0402]  159.11 76.76 180 top
C1713  1uF/10V_2  [0402]  140.32 68.67 180 top
C1714  1nF/50V_2  [0402]  139.83 65.95 270 top
C1715  1uF/10V_2  [0402]  139.01 65.95 270 top
C1716  100nF/16V_2  [0402]  140.66 65.96 270 top
C1717  100nF/16V_2  [0402]  140.23 60.12 180 top
C1718  NC 10uF/10V_2  [0402W]  148.2 77 0 top
C1719  1uF/10V_2  [0402]  148.24 76.02 0 top
C1720  10nF/50V_2  [0402]  143.35 54.45 180 top
C1721  10nF/50V_2  [0402]  140.5 61.47 90 top
C1722  10nF/50V_2  [0402]  148.24 75.18 0 top
C1723  10nF/50V_2  [0402]  157.79 75.49 90 top
C1724  1nF/50V_2  [0402]  161.81 63.93 0 top
C1725  1uF/10V_2  [0402]  161.81 65.06 0 top
C1726  1nF/50V_2  [0402]  139 63.3 90 top
C1727  10uF/10V_2  [0402W]  138 63.3 90 top
C1728  10uF/10V_2  [0402W]  136.85 63.3 90 top
C1729  1uF/10V_2  [0402]  161.81 61.73 0 top
C1730  1uF/10V_2  [0402]  161.81 69.14 0 top
C1731  NC 10uF/10V_2  [0402W]  161.84 70.1 0 top
C1732  100nF/16V_2  [0402]  155.27 75.48 90 top
C1733  100nF/16V_2  [0402]  152.77 75.5 90 top
C1734  100nF/16V_2  [0402]  145.37 75.54 90 top
C1735  100nF/16V_2  [0402]  157.75 53.99 270 top
C1736  100nF/16V_2  [0402]  161.81 62.58 0 top
C1737  100nF/16V_2  [0402]  161.8 68.28 0 top
C1738  10nF/50V_2  [0402]  140.66 67.48 90 top
C1739  1uF/10V_2  [0402]  139.85 67.48 90 top
C1740  1nF/50V_2  [0402]  139.75 72.95 90 top
C1741  1uF/10V_2  [0402]  161.75 59.46 0 top
C1742  1uF/10V_2  [0402]  161.76 72.4 0 top
C1743  1uF/10V_2  [0402]  146.21 75.54 90 top
C1744  1uF/10V_2  [0402]  150.27 75.51 90 top
C1745  100nF/16V_2  [0402]  161.75 71.53 0 top
C1746  100nF/16V_2  [0402]  161.81 65.9 0 top
C1747  100nF/16V_2  [0402]  161.75 60.3 0 top
C1748  100nF/16V_2  [0402]  156.63 53.99 270 top
C1749  100nF/16V_2  [0402]  149.24 53.08 270 top
C1750  100nF/16V_2  [0402]  140.29 70.83 180 top
C1751  100nF/16V_2  [0402]  149.42 75.52 90 top
C1752  100nF/16V_2  [0402]  147.03 75.54 90 top
C1753  100nF/16V_2  [0402]  154.44 75.5 90 top
C1754  100nF/10V_1  [0201]  140.56 69.41 180 top
C1755  100nF/10V_1  [0201]  140.56 69.99 180 top
C1800  1uF/10V_2  [0402]  147.05 79.47 0 top
C1801  1uF/10V_2  [0402]  131.25 51.17 0 top
C1802  1uF/10V_2  [0402]  127.05 54.87 180 top
C1803  1uF/10V_2  [0402]  137.5 27.42 90 top
C1808  100nF/16V_2  [0402]  138.33 27.42 90 top
C1900  1nF/2KV_6  [SC1206]  170.25 75.47 0 top
C1901  1nF/2KV_6  [SC1206]  170.58 98.17 0 top
C2000  1nF/2KV_6  [SC1206]  170.25 54.27 0 top
C2001  1nF/2KV_6  [SC1206]  170.2 31.42 0 top
C2300  100nF/16V_2  [0402]  162.54 47.18 270 bottom
C2301  1nF/50V_2  [0402]  125.45 35.47 0 top
C2302  22uF/10V_3  [SC0603DE-H1_1]  163.85 47.35 270 bottom
C2303  100nF/16V_2  [0402]  142.89 47.78 270 bottom
C2304  2.2uF/10V_2  [0402]  128.05 38.07 270 top
C2305  12pF/50V_2  [0402]  110.4 98.48 0 bottom
C2306  22uF/10V_3  [SC0603DE-H1_1]  148.69 47.92 270 bottom
C2307  1uF/10V_2  [0402]  130.34 45.35 90 top
C2308  100nF/16V_2  [0402]  130.34 49.05 270 top
C2309  12pF/50V_2  [0402]  108.8 98.48 180 bottom
C2313  1uF/10V_2  [0402]  127.87 44.23 180 top
C2314  22uF/10V_3  [SC0603DE-H1_1]  144.09 47.98 270 bottom
C2315  100nF/16V_2  [0402]  127.27 49.03 270 top
C2399  NC 1uF/10V_2  [0402]  125.55 40.77 180 top
C2400  100nF/10V_1  [0201]  148.8 88.76 180 top
C2401  12pF/50V_2  [0402]  146.52 92.83 90 top
C2402  12pF/50V_2  [0402]  146.52 91.23 270 top
C2403  100nF/10V_1  [0201]  148.8 88.19 180 top
C2404  100nF/10V_1  [0201]  154.51 95.99 90 top
C2405  100nF/10V_1  [0201]  153.91 95.99 90 top
C2406  100nF/10V_1  [0201]  156.91 95.96 90 top
C2407  100nF/16V_2  [0402]  161.8 80.8 180 top
C2408  100nF/10V_1  [0201]  157.48 95.96 90 top
C2409  100nF/10V_1  [0201]  161.48 90.97 0 top
C2410  100nF/10V_1  [0201]  161.48 90.39 0 top
C2411  100nF/10V_1  [0201]  161.37 86.99 0 top
C2412  100nF/10V_1  [0201]  161.37 86.39 0 top
C2413  1uF/10V_2  [0402]  149.55 79.07 0 top
C2414  2.2uF/10V_2  [0402]  161.4 89.55 180 top
C2415  100nF/16V_2  [0402]  155.3 95.9 90 top
C2416  100nF/16V_2  [0402]  148.56 89.47 180 top
C2417  100nF/16V_2  [0402]  156.1 83.35 270 top
C2418  100nF/16V_2  [0402]  145.1 88.35 270 top
C2419  10nF/50V_2  [0402]  145.95 88.35 270 top
C2420  2.2uF/10V_2  [0402]  149.11 82.94 180 top
C2421  100nF/16V_2  [0402]  158.25 95.9 90 top
C2422  100nF/16V_2  [0402]  148.56 91.12 180 top
C2423  100nF/16V_2  [0402]  152.8 83.35 270 top
C2424  100nF/16V_2  [0402]  157.6 83.35 270 top
C2425  10nF/50V_2  [0402]  161.4 92.65 0 top
C2426  2.2uF/10V_2  [0402]  147.19 85.68 90 top
C2427  100nF/16V_2  [0402]  161.4 88.25 0 top
C2428  100nF/16V_2  [0402]  161.4 91.75 0 top
C2429  100nF/16V_2  [0402]  156.15 95.9 90 top
C2430  100nF/16V_2  [0402]  153.05 95.9 90 top
C2431  100nF/16V_2  [0402]  152.15 95.9 90 top
C2432  100nF/16V_2  [0402]  147.85 87.4 90 top
C2433  10nF/50V_2  [0402]  147 87.4 90 top
C2434  10nF/50V_2  [0402]  146.34 85.67 270 top
C2500  2.2uF/10V_2  [0402]  123.44 56.43 0 bottom
C2501  10uF/10V_2  [0402W]  123.49 50.98 0 bottom
C2502  100nF/16V_2  [0402]  123.49 50.03 180 bottom
C2503  2.2uF/10V_2  [0402]  136.8 72.84 90 bottom
C2505  100nF/16V_2  [0402]  136.15 78.42 180 bottom
C2506  10uF/10V_2  [0402W]  129.8 55.84 90 bottom
C2507  100nF/16V_2  [0402]  128.75 55.74 90 bottom
C2508  100nF/16V_2  [0402]  132.6 48.19 270 bottom
C2509  2.2uF/10V_2  [0402]  132.35 72.89 90 bottom
C2511  100nF/16V_2  [0402]  131.85 78.42 180 bottom
C2512  1uF/10V_2  [0402]  130.75 55.79 90 bottom
C2513  2.2uF/10V_2  [0402]  136.65 62.44 90 bottom
C2515  100nF/16V_2  [0402]  137.15 68.12 0 bottom
C2516  1uF/10V_2  [0402]  133.45 48.19 270 bottom
C2517  NC 12pF/50V_2  [0402]  135.87 46.97 0 bottom
C2518  NC 12pF/50V_2  [0402]  134.32 46.97 180 bottom
C2519  2.2uF/10V_2  [0402]  132.15 62.44 90 bottom
C2521  100nF/16V_2  [0402]  132.65 68.07 0 bottom
C2522  NC 100nF/16V_2  [0402]  130.57 51.07 180 bottom
C2696  1uF/50V_3  [SC0603A-H0_9]  92.75 53.25 90 bottom
C2697  10uF/50V_5  [SC0805H1_45]  88.55 47.95 180 bottom
C2698  22uF/35V_5  [SC0805]  88.55 49.6 180 bottom
C2699  22uF/35V_5  [SC0805]  91.25 53.45 90 bottom
C2700  2.2uF/10V_2  [0402]  139.88 108.12 270 top
C2701  2.2uF/10V_2  [0402]  166.28 119.34 180 top
C2703  100nF/16V_2  [0402]  140.33 101.67 0 top
C2705  100nF/16V_2  [0402]  159.68 118.89 270 top
C2706  2.2uF/10V_2  [0402]  152.05 112.33 180 top
C2707  2.2uF/10V_2  [0402]  150.34 102.1 90 top
C2708  100nF/16V_2  [0402]  145.4 111.88 270 top
C2711  100nF/16V_2  [0402]  149.89 108.94 180 top
C2800  10uF/10V_2  [0402W]  86.6 96.9 270 bottom
C2801  100nF/16V_2  [0402]  85.65 96.95 270 bottom
C2802  100nF/50V_2  [0402]  87.25 103.8 270 bottom
C2803  1nF/50V_2  [0402]  88.1 103.8 270 bottom
C2804  10uF/50V_5  [SC0805H1_45]  89.35 103.55 270 bottom
C2805  10uF/50V_5  [SC0805H1_45]  91 103.55 270 bottom
C2806  12pF/50V_2  [0402]  98.74 17.69 270 bottom
C2807  12pF/50V_2  [0402]  98.74 16.14 270 bottom
C2808  100nF/16V_2  [0402]  107.15 17.1 270 bottom
C2809  100nF/16V_2  [0402]  97.45 21.3 90 bottom
C2810  1uF/10V_2  [0402]  83.65 96.95 270 bottom
C2811  220nF/50V_3  [SC0603]  88.5 109.55 0 bottom
C2812  680nF/50V_5  [SC0805]  88.65 121 90 bottom
C2813  680nF/50V_5  [SC0805]  94.95 121 90 bottom
C2814  1nF/50V_2  [0402]  87.4 120.7 90 bottom
C2815  1nF/50V_2  [0402]  93.7 120.7 90 bottom
C2816  220nF/50V_3  [SC0603]  82.75 109.55 0 bottom
C2817  220nF/50V_3  [SC0603]  80.5 109.55 180 bottom
C2818  10nF/50V_2  [0402]  86.95 121.9 180 bottom
C2819  10nF/50V_2  [0402]  93.25 121.9 180 bottom
C2820  220nF/50V_3  [SC0603]  74.75 109.55 180 bottom
C2821  680nF/50V_5  [SC0805]  67.9 121 90 bottom
C2822  680nF/50V_5  [SC0805]  74.8 121 90 bottom
C2823  1nF/50V_2  [0402]  69.2 120.65 90 bottom
C2824  1nF/50V_2  [0402]  76.05 120.65 90 bottom
C2825  100nF/50V_2  [0402]  76.05 103.85 270 bottom
C2826  1nF/50V_2  [0402]  75.2 103.85 270 bottom
C2827  10uF/50V_5  [SC0805H1_45]  73.95 103.6 270 bottom
C2828  10uF/50V_5  [SC0805H1_45]  72.3 103.6 270 bottom
C2829  1uF/10V_2  [0402]  76.5 96.95 90 bottom
C2830  10nF/50V_2  [0402]  69.65 121.85 0 bottom
C2831  10nF/50V_2  [0402]  76.5 121.85 0 bottom
C2838  100nF/16V_2  [0402]  75.65 96.95 90 bottom
C2900  10uF/25V_3  [SC0603A-H0_9]  24.51 103.54 90 bottom
C2901  100nF/50V_2  [0402]  22.61 103.36 90 bottom
C2902  10nF/50V_2  [0402]  23.45 103.36 90 bottom
C2903  47uF/6.3V_3  [SC0603BC-H1_0]  33.79 103.54 225 bottom
C2904  100nF/16V_2  [0402]  36.07 101.71 225 bottom
C2905  100nF/16V_2  [0402]  36.67 101.11 225 bottom
C2906  10uF/10V_2  [0402W]  37.4 100.3 225 bottom
C2907  10nF/50V_2  [0402]  37.7 90.54 225 bottom
C2908  100nF/50V_2  [0402]  38.47 102.25 135 bottom
C2909  100nF/50V_2  [0402]  37.87 101.64 135 bottom
C2910  100nF/16V_2  [0402]  39.57 102.88 45 bottom
C2911  10nF/50V_2  [0402]  38.99 103.45 45 bottom
C2912  47uF/6.3V_3  [SC0603BC-H1_0]  35.6 106.57 135 bottom
C2913  100nF/16V_2  [0402]  48.8 91.32 90 bottom
C2914  10nF/50V_2  [0402]  47.94 91.32 90 bottom
C2915  47uF/6.3V_3  [SC0603BC-H1_0]  52.3 91.89 90 bottom
C2916  10uF/10V_2  [0402W]  36.34 90.49 225 bottom
C2917  100nF/16V_2  [0402]  37.09 91.6 135 bottom
C2918  10nF/50V_2  [0402]  35.7 100.4 135 bottom
C2919  10uF/25V_3  [SC0603A-H0_9]  27.31 89.71 270 bottom
C2920  100nF/50V_2  [0402]  26.26 89.85 270 bottom
C2921  10nF/50V_2  [0402]  25.42 89.85 270 bottom
C2922  10nF/50V_2  [0402]  48.98 98.16 135 bottom
C2923  100nF/16V_2  [0402]  49.57 98.75 135 bottom
C2924  47uF/6.3V_3  [SC0603BC-H1_0]  51.27 101.07 135 bottom
C2925  100nF/50V_2  [0402]  34.86 98.78 135 bottom
C2926  100nF/50V_2  [0402]  35.5 99.42 135 bottom
C2927  10uF/25V_3  [SC0603A-H0_9]  25.84 87.47 90 bottom
C2928  100nF/50V_2  [0402]  24.79 87.25 90 bottom
C2929  10nF/50V_2  [0402]  23.95 87.25 90 bottom
C2930  100nF/50V_2  [0402]  35.36 92.81 225 bottom
C2931  100nF/50V_2  [0402]  35.96 92.2 225 bottom
C2932  10uF/25V_3  [SC0603A-H0_9]  26.93 78.6 270 bottom
C2933  100nF/50V_2  [0402]  25.88 78.74 270 bottom
C2934  100nF/16V_2  [0402]  33.47 95.52 135 bottom
C2935  10nF/50V_2  [0402]  32.9 94.94 135 bottom
C2936  10nF/50V_2  [0402]  25.04 78.74 270 bottom
C2937  100nF/50V_2  [0402]  38.97 89.27 225 bottom
C2938  100nF/50V_2  [0402]  38.33 89.91 225 bottom
C2939  10uF/10V_2  [0402W]  46.91 91.27 90 bottom
C2940  NC 12pF/50V_2  [0402]  32.99 98.71 45 bottom
C2941  NC 12pF/50V_2  [0402]  31.86 97.58 225 bottom
C2942  10uF/10V_2  [0402W]  38.35 104.17 45 bottom
C3000  10uF/25V_3  [SC0603A-H0_9]  23.62 74.42 270 bottom
C3001  100nF/50V_2  [0402]  22.57 74.66 270 bottom
C3002  10nF/50V_2  [0402]  21.73 74.66 270 bottom
C3003  47uF/6.3V_3  [SC0603BC-H1_0]  33.08 80.34 135 bottom
C3004  100nF/16V_2  [0402]  33.46 75.31 225 bottom
C3005  100nF/16V_2  [0402]  34.06 74.71 225 bottom
C3006  10uF/10V_2  [0402W]  34.65 73.95 225 bottom
C3007  10nF/50V_2  [0402]  35.09 64.13 225 bottom
C3008  100nF/50V_2  [0402]  35.86 75.84 135 bottom
C3009  100nF/50V_2  [0402]  35.26 75.24 135 bottom
C3010  47uF/6.3V_3  [SC0603BC-H1_0]  45.45 62.12 135 bottom
C3011  100nF/16V_2  [0402]  43.57 62.76 45 bottom
C3012  10nF/50V_2  [0402]  42.96 63.37 45 bottom
C3013  10uF/25V_3  [SC0603A-H0_9]  27.77 68.94 90 bottom
C3014  100nF/50V_2  [0402]  25.87 68.8 90 bottom
C3015  47uF/6.3V_3  [SC0603BC-H1_0]  31.18 77.13 225 bottom
C3016  100nF/16V_2  [0402]  36.96 76.47 45 bottom
C3017  10nF/50V_2  [0402]  36.38 77.05 45 bottom
C3018  10uF/10V_2  [0402W]  33.72 64.08 225 bottom
C3019  100nF/16V_2  [0402]  34.48 65.2 135 bottom
C3020  10nF/50V_2  [0402]  33 74.1 135 bottom
C3021  10nF/50V_2  [0402]  26.71 68.8 90 bottom
C3022  100nF/50V_2  [0402]  32.25 72.37 135 bottom
C3023  100nF/50V_2  [0402]  32.89 73.01 135 bottom
C3024  47uF/6.3V_3  [SC0603BC-H1_0]  49.66 73.24 315 bottom
C3025  100nF/16V_2  [0402]  47.31 71.49 315 bottom
C3026  10nF/50V_2  [0402]  46.72 70.9 315 bottom
C3027  10uF/25V_3  [SC0603A-H0_9]  26.27 62.29 270 bottom
C3028  100nF/50V_2  [0402]  25.22 62.42 270 bottom
C3029  10nF/50V_2  [0402]  24.38 62.42 270 bottom
C3030  100nF/50V_2  [0402]  32.75 66.4 225 bottom
C3031  100nF/50V_2  [0402]  33.35 65.8 225 bottom
C3032  NC 12pF/50V_2  [0402]  30.38 72.3 45 bottom
C3033  NC 12pF/50V_2  [0402]  29.25 71.17 225 bottom
C3034  10uF/25V_3  [SC0603A-H0_9]  27.09 52.98 270 bottom
C3035  100nF/50V_2  [0402]  26.04 53.12 270 bottom
C3036  10nF/50V_2  [0402]  25.2 53.12 270 bottom
C3037  100nF/50V_2  [0402]  36.36 62.86 225 bottom
C3038  100nF/50V_2  [0402]  35.72 63.5 225 bottom
C3039  10uF/10V_2  [0402W]  42.3 64.15 45 bottom
C3040  10uF/10V_2  [0402W]  35.75 77.77 45 bottom
C3044  10uF/25V_3  [SC0603A-H0_9]  23.26 76.69 180 top
C3045  10uF/25V_3  [SC0603A-H0_9]  23.26 74.89 180 top
C3049  100nF/16V_2  [0402]  26.49 73.61 180 top
C3100  10uF/25V_3  [SC0603A-H0_9]  29.62 101.79 90 top
C3101  10uF/25V_3  [SC0603A-H0_9]  27.82 101.79 90 top
C3102  100nF/16V_2  [0402]  26.62 98.57 90 top
C3103  10uF/25V_3  [SC0603A-H0_9]  23.23 93.57 180 top
C3104  10uF/25V_3  [SC0603A-H0_9]  23.23 91.77 180 top
C3105  100nF/16V_2  [0402]  26.48 90.59 180 top
C3106  10uF/25V_3  [SC0603A-H0_9]  23.25 87.89 180 top
C3107  10uF/25V_3  [SC0603A-H0_9]  23.25 86.09 180 top
C3108  100nF/16V_2  [0402]  26.48 84.8 180 top
C3109  10uF/25V_3  [SC0603A-H0_9]  23.27 82.28 180 top
C3110  10uF/25V_3  [SC0603A-H0_9]  23.27 80.48 180 top
C3111  100nF/16V_2  [0402]  26.5 79.2 180 top
C3112  1uF/10V_2  [0402]  38.53 55.84 0 bottom
C3113  100nF/16V_2  [0402]  38.53 52.44 0 bottom
C3200  10uF/10V_2  [0402W]  55.1 65.54 90 bottom
C3201  22uF/10V_3  [SC0603DE-H1_1]  51.3 64.17 270 bottom
C3202  22uF/10V_3  [SC0603DE-H1_1]  49.85 64.17 270 bottom
C3203  100nF/16V_2  [0402]  47.2 64.92 180 bottom
C3204  10uF/10V_2  [0402W]  47.3 107.57 180 bottom
C3205  1nF/50V_2  [0402]  44.75 104.84 90 bottom
C3206  22uF/10V_3  [SC0603DE-H1_1]  44.5 107.37 90 bottom
C3207  100nF/16V_2  [0402]  43.35 107.24 90 bottom
C3208  1uF/10V_2  [0402]  55.12 105.42 0 bottom
C3209  100nF/16V_2  [0402]  55.17 99.87 0 bottom
C3210  NC 6.8pF/50V_2  [0402]  52.29 60.47 90 bottom
C3221  10nF/50V_2  [0402]  56.72 99.87 180 bottom
C3229  NC 100nF/50V_2  [0402]  55.83 60.49 270 bottom
C3230  10uF/25V_3  [SC0603A-H0_9]  23.23 70.46 180 top
C3231  10uF/25V_3  [SC0603A-H0_9]  23.23 68.66 180 top
C3232  100nF/16V_2  [0402]  26.46 67.38 180 top
C3233  10uF/25V_3  [SC0603A-H0_9]  23.26 64.59 180 top
C3234  10uF/25V_3  [SC0603A-H0_9]  23.26 62.79 180 top
C3235  100nF/16V_2  [0402]  26.5 61.45 180 top
C3236  10uF/25V_3  [SC0603A-H0_9]  23.26 57.86 180 top
C3237  10uF/25V_3  [SC0603A-H0_9]  23.26 56.06 180 top
C3238  100nF/16V_2  [0402]  26.48 54.78 180 top
C3400  1uF/10V_2  [0402]  130.77 112.16 90 bottom
C3401  1uF/10V_2  [0402]  133.16 107.95 180 bottom
C3404  22pF/50V_2  [0402]  132.3 120.77 180 bottom
C3405  22pF/50V_2  [0402]  133.99 120.78 0 bottom
C3406  RES_PAD_6  [1206_SP]  129.97 119.64 90 bottom
C3407  1uF/10V_2  [0402]  122.4 112.09 90 bottom
C3408  1uF/10V_2  [0402]  124.96 107.94 180 bottom
C3411  22pF/50V_2  [0402]  124.1 120.78 180 bottom
C3412  22pF/50V_2  [0402]  125.79 120.79 0 bottom
C3413  RES_PAD_6  [1206_SP]  121.66 119.71 90 bottom
C3414  1uF/10V_2  [0402]  114.82 112.17 90 bottom
C3415  1uF/10V_2  [0402]  117.39 107.95 180 bottom
C3416  22pF/50V_2  [0402]  116.52 120.78 180 bottom
C3417  22pF/50V_2  [0402]  118.21 120.79 0 bottom
C3418  RES_PAD_6  [1206_SP]  114.2 119.66 90 bottom
C3419  1uF/10V_2  [0402]  107.71 112.16 90 bottom
C3420  1uF/10V_2  [0402]  110.15 107.94 180 bottom
C3421  22pF/50V_2  [0402]  109.28 120.77 180 bottom
C3422  22pF/50V_2  [0402]  110.98 120.77 0 bottom
C3423  RES_PAD_6  [1206_SP]  106.83 119.61 90 bottom
C3424  1uF/10V_2  [0402]  135.4 101.6 270 bottom
C3425  100nF/16V_2  [0402]  135.5 96.52 270 bottom
C3426  1uF/10V_2  [0402]  135.5 98.05 90 bottom
C3427  12pF/50V_2  [0402]  140.59 105.66 0 bottom
C3428  12pF/50V_2  [0402]  139.07 105.66 180 bottom
C3429  100nF/16V_2  [0402]  109.75 89.04 180 bottom
C3430  1uF/10V_2  [0402]  112.03 89.04 0 bottom
C3431  1uF/10V_2  [0402]  124.8 101.6 270 bottom
C3432  100nF/16V_2  [0402]  128.86 96.76 270 bottom
C3433  1uF/10V_2  [0402]  128.87 98.31 90 bottom
C3434  1uF/10V_2  [0402]  105.65 94.6 270 bottom
C3435  100nF/16V_2  [0402]  135.5 91.68 270 bottom
C3436  100nF/16V_2  [0402]  135.5 93.23 90 bottom
C3437  1uF/10V_2  [0402]  105.7 102.9 270 bottom
C3438  100nF/16V_2  [0402]  128.99 91.91 270 bottom
C3439  100nF/16V_2  [0402]  128.99 93.44 90 bottom
C3498  12pF/50V_2  [0402]  128.15 106.65 180 bottom
C3499  12pF/50V_2  [0402]  113.15 107.6 90 bottom
C3500  2.2nF/50V_2  [0402]  85.55 112.55 180 top
C3501  4.7uF/35V_3  [SC0603DE-H1_0]  85.15 115.85 270 top
C3502  1uF/35V_2  [0402]  85.15 107.4 270 top
C3503  4.7uF/35V_3  [SC0603DE-H1_0]  83.35 115.8 270 top
C3504  1uF/35V_2  [0402]  83.35 107.35 270 top
C3505  2.2nF/50V_2  [0402]  82.95 112.5 180 top
C3506  2.2nF/50V_2  [0402]  77.15 112.5 180 top
C3507  1uF/10V_2  [0402]  94.75 96.6 0 top
C3508  4.7uF/35V_3  [SC0603DE-H1_0]  76.75 115.8 270 top
C3509  1uF/35V_2  [0402]  76.75 107.35 270 top
C3510  4.7uF/35V_3  [SC0603DE-H1_0]  75.05 115.8 270 top
C3511  1uF/35V_2  [0402]  75.05 107.35 270 top
C3512  2.2nF/50V_2  [0402]  74.65 112.5 180 top
C3513  1uF/10V_2  [0402]  94.75 95.75 0 top
C3514  10uF/10V_2  [0402W]  88 91.3 270 top
C3515  100nF/16V_2  [0402]  89 91.3 90 top
C3516  1uF/10V_2  [0402]  95.3 92.75 270 top
C3517  100nF/16V_2  [0402]  94.45 92.75 90 top
C3518  10uF/10V_2  [0402W]  95.4 94.45 90 top
C3519  100nF/16V_2  [0402]  94.45 94.45 270 top
C3520  10uF/10V_2  [0402W]  93.2 90.75 0 top
C3521  100nF/16V_2  [0402]  93.1 91.7 180 top
C3522  NC 1uF/10V_2  [0402]  50.35 106.54 270 top
C3523  10uF/10V_2  [0402W]  48.4 122.54 0 top
C3524  100nF/16V_2  [0402]  48.4 123.51 180 top
C3525  1uF/10V_2  [0402]  49.35 116.19 90 top
C3526  1uF/10V_2  [0402]  50.57 115.82 180 top
C3527  10uF/10V_2  [0402W]  56.17 109.39 270 top
C3528  100nF/16V_2  [0402]  55.15 109.4 90 top
C3529  1uF/10V_2  [0402]  53.98 116.82 0 top
C3530  100nF/16V_2  [0402]  53.97 115.92 180 top
C3531  10uF/10V_2  [0402W]  52.15 116.8 180 top
C3532  100nF/16V_2  [0402]  52.13 115.82 0 top
C3533  10uF/10V_2  [0402W]  56.13 114.44 90 top
C3534  100nF/16V_2  [0402]  55.15 114.45 270 top
C3535  10uF/10V_2  [0402W]  30.01 122.59 0 top
C3536  100nF/16V_2  [0402]  30 123.55 180 top
C3623  100nF/16V_2  [0402]  125.36 7.92 270 top
C3624  100nF/16V_2  [0402]  130.59 7.24 270 top
C3625  1uF/10V_2  [0402]  134.72 9.44 270 top
C3626  100nF/50V_2  [0402]  166.79 8.05 270 top
C3627  4.7uF/16V_2  [0402W]  180.2 8.1 90 top
C3628  4.7uF/16V_2  [0402W]  165.85 8.07 90 top
C3903  2.2uF/10V_2  [0402]  129.77 108.62 180 top
C4000  100nF/50V_2  [0402]  144.57 115.61 180 top
C4001  2.2uF/10V_2  [0402]  134.22 115.51 180 top
C4002  100nF/50V_2  [0402]  144.57 116.46 180 top
C4003  100nF/50V_2  [0402]  144.25 117.89 270 top
C4004  100nF/50V_2  [0402]  144.57 119.11 180 top
C4005  100nF/16V_2  [0402]  132.94 105.52 180 top
C4006  1uF/10V_2  [0402]  132.95 104.68 180 top
C4007  1uF/10V_2  [0402]  127.14 104.77 180 top
C4008  100nF/16V_2  [0402]  127.14 105.62 180 top
C4009  1uF/10V_2  [0402]  143.84 111.71 90 top
CM2000  90R/0.1A  [CMC4-0_4-0_65X0_5H0_35]  170.9 70.69 90 top
CM2001  90R/0.1A  [CMC4-0_4-0_65X0_5H0_35]  170.85 46.42 270 top
CM2002  90R/0.1A  [CMC4-0_4-0_65X0_5H0_35]  170.9 67.54 90 top
CM2003  90R/0.1A  [CMC4-0_4-0_65X0_5H0_35]  170.77 49.22 90 top
CM2701  90R/0.1A  [CMC4-0_4-0_65X0_5H0_35]  170.48 90.51 270 top
CM2705  90R/0.1A  [CMC4-0_4-0_65X0_5H0_35]  170.72 109.75 270 top
CM2708  90R/0.1A  [CMC4-0_4-0_65X0_5H0_35]  167.46 116.56 270 top
CM2710  90R/0.1A  [CMC4-0_4-0_65X0_5H0_35]  167.32 94.01 270 top
CM3400  2000R/0.15A  [EMC4_4_5X3_2H3]  133.15 117.08 90 bottom
CM3401  2000R/0.15A  [EMC4_4_5X3_2H3]  124.95 117.09 90 bottom
CM3402  2000R/0.15A  [EMC4_4_5X3_2H3]  117.37 117.09 90 bottom
CM3403  2000R/0.15A  [EMC4_4_5X3_2H3]  110.13 117.08 90 bottom
CMC1200  1.3R/0.1A  [CMC4-0_65X0_5H0_3]  12.1 14.04 90 top
CMC1201  1.3R/0.1A  [CMC4-0_65X0_5H0_3]  13.6 14.04 90 top
CMC1202  1.3R/0.1A  [CMC4-0_65X0_5H0_3]  15.15 14.04 90 top
CMC1203  1.3R/0.1A  [CMC4-0_65X0_5H0_3]  16.65 14.04 90 top
CMC1204  1.3R/0.1A  [CMC4-0_65X0_5H0_3]  25.65 28.77 180 top
CMC1205  1.3R/0.1A  [CMC4-0_65X0_5H0_3]  25.65 30.27 180 top
CMC1206  1.3R/0.1A  [CMC4-0_65X0_5H0_3]  25.65 31.92 180 top
CMC1207  1.3R/0.1A  [CMC4-0_65X0_5H0_3]  25.65 33.42 180 top
CMC1300  1.3R/0.1A  [CMC4-0_65X0_5H0_3]  25.33 41.54 180 top
CMC1301  1.3R/0.1A  [CMC4-0_65X0_5H0_3]  25.33 43.04 180 top
CMC1302  1.3R/0.1A  [CMC4-0_65X0_5H0_3]  25.33 44.59 180 top
CMC1303  1.3R/0.1A  [CMC4-0_65X0_5H0_3]  25.33 46.09 180 top
CMC2700  1.3R/0.1A  [CMC4-0_65X0_5H0_3]  170.15 88.82 0 top
CMC2702  1.3R/0.1A  [CMC4-0_65X0_5H0_3]  170.17 93.68 0 top
CMC2703  1.3R/0.1A  [CMC4-0_65X0_5H0_3]  170.16 87.36 0 top
CMC2704  1.3R/0.1A  [CMC4-0_65X0_5H0_3]  170.42 112.96 0 top
CMC2706  1.3R/0.1A  [CMC4-0_65X0_5H0_3]  170.4 116.37 0 top
CMC2707  1.3R/0.1A  [CMC4-0_65X0_5H0_3]  170.42 111.43 0 top
CMC2709  1.3R/0.1A  [CMC4-0_65X0_5H0_3]  170.41 114.87 0 top
CMC2711  1.3R/0.1A  [CMC4-0_65X0_5H0_3]  170.16 92.18 0 top
CN2300  APCIA178-P001BC  [PCI75-H4_9-APCIA178]  153.29 40.58 0 bottom
CON2900  A-M4008T-4-A  [CON4-12X24_3H14_4-M4008T-4]  7.25 87 180 top
CON3000  A-M4008T-4-A  [CON4-12X24_3H14_4-M4008T-4]  7.25 67 180 top
CR1200  PESDALC10N5VU  [DFN10-0_5-2_5X1H0_55]  12.85 15.49 180 top
CR1201  PESDALC10N5VU  [DFN10-0_5-2_5X1H0_55]  15.9 15.49 180 top
CR1207  PESDALC10N5VU  [DFN10-0_5-2_5X1H0_55]  24.2 29.52 270 top
CR1208  PESDALC10N5VU  [DFN10-0_5-2_5X1H0_55]  24.2 32.67 270 top
CR1300  PESDALC10N5VU  [DFN10-0_5-2_5X1H0_55]  23.93 42.29 270 top
CR1301  PESDALC10N5VU  [DFN10-0_5-2_5X1H0_55]  23.93 45.34 270 top
CR1500  PESDALC10N5VU  [DFN10-0_5-2_5X1H0_55]  21.8 111.65 270 top
CR1501  PESDALC10N5VU  [DFN10-0_5-2_5X1H0_55]  21.8 107.25 270 top
CR1900  PESDALC10N5VU  [DFN10-0_5-2_5X1H0_55]  171.84 104.17 90 top
CR1901  PESDALC10N5VU  [DFN10-0_5-2_5X1H0_55]  171.58 82.06 90 top
CR1902  PESDALC10N5VU  [DFN10-0_5-2_5X1H0_55]  171.84 107.29 90 top
CR1903  PESDALC10N5VU  [DFN10-0_5-2_5X1H0_55]  171.58 85.08 90 top
CR1904  PESDALC10N5VU  [DFN10-0_5-2_5X1H0_55]  171.58 88.09 270 top
CR1905  PESDALC10N5VU  [DFN10-0_5-2_5X1H0_55]  171.83 112.19 270 top
CR1906  PESDALC10N5VU  [DFN10-0_5-2_5X1H0_55]  171.59 92.95 270 top
CR1907  PESDALC10N5VU  [DFN10-0_5-2_5X1H0_55]  171.84 115.6 270 top
CR2000  PESDALC10N5VU  [DFN10-0_5-2_5X1H0_55]  171.5 61.5 90 top
CR2001  PESDALC10N5VU  [DFN10-0_5-2_5X1H0_55]  171.38 39.62 90 top
CR2002  PESDALC10N5VU  [DFN10-0_5-2_5X1H0_55]  171.5 64.65 90 top
CR2003  PESDALC10N5VU  [DFN10-0_5-2_5X1H0_55]  171.43 42.82 90 top
CR2300  PESDALC10N5VU  [DFN10-0_5-2_5X1H0_55]  152.04 34.08 180 bottom
CR2304  PESDALC10N5VU  [DFN10-0_5-2_5X1H0_55]  158.04 34.08 180 bottom
CR2305  PESDALC10N5VU  [DFN10-0_5-2_5X1H0_55]  155.04 34.08 180 bottom
CR2307  PESDALC10N5VU  [DFN10-0_5-2_5X1H0_55]  146.04 34.08 180 bottom
CR2308  PESDALC10N5VU  [DFN10-0_5-2_5X1H0_55]  149.04 34.08 180 bottom
CT501  330uF/50V  [SC-10_3X10_3H10_5]  134.9 34.35 270 bottom
CT700  47uF/50V  [SC-6_6X6_6H8_0]  115.8 36.25 90 bottom
CT701  47uF/50V  [SC-6_6X6_6H8_0]  88.05 43.5 0 bottom
CT1900  100uF/16V  [SC-6_6X6_6H8_0]  171.35 99.57 90 bottom
CT1901  100uF/16V  [SC-6_6X6_6H8_0]  171.35 77.47 90 bottom
CT1902  100uF/16V  [SC-6_6X6_6H8_0]  171.35 109.07 270 bottom
CT1903  100uF/16V  [SC-6_6X6_6H8_0]  171.35 86.97 270 bottom
CT2500  100uF/16V  [SC-6_6X6_6H8_0]  171.35 65.87 270 bottom
CT2501  100uF/16V  [SC-6_6X6_6H8_0]  171.35 56.37 90 bottom
CT2502  100uF/16V  [SC-6_6X6_6H8_0]  171.35 44.97 270 bottom
CT2503  100uF/16V  [SC-6_6X6_6H8_0]  171.35 35.47 90 bottom
CT2700  390uF/35V  [SC-10_3X10_3H10_5]  98.35 101.2 180 bottom
CT2701  390uF/35V  [SC-10_3X10_3H10_5]  64.8 101.2 0 bottom
D500  SMCJ28CA  [DO-214AB-H2_82-SMCJ12CA]  169.08 17.2 90 bottom
D501  SMCJ28CA  [DO-214AB-H2_82-SMCJ12CA]  174.13 13.38 0 top
D502  LMBR140FT1G  [SOD123H1_4]  127.07 14.79 270 bottom
D503  LMBR140FT1G  [SOD123H1_4]  95.01 64.99 0 bottom
D504  LMBR140FT1G  [SOD123H1_4]  97.08 74.41 90 bottom
D505  SMCJ28CA  [DO-214AB-H2_82-SMCJ12CA]  173.18 22.52 270 top
D506  LMBR140FT1G  [SOD123H1_4]  176.39 122.02 180 top
D507  ESD9N18BA-2/TR  [DFN1006-2L-H0_5]  141.65 23.65 270 bottom
D508  LMBR140FT1G  [SOD123H1_4]  134.6 14.75 180 bottom
D509  LMBR140FT1G  [SOD123H1_4]  139.2 19.05 180 bottom
D600  NC LMBR140FT1G  [SOD123H1_4]  74.79 56.66 0 bottom
D900  WSB5557Z-2/TR  [DFN0603-2L-H0_34]  21.65 13.34 180 top
D1100  WSB5557Z-2/TR  [DFN0603-2L-H0_34]  29.53 45.02 0 bottom
D1200  WSB5557Z-2/TR  [DFN0603-2L-H0_34]  28.71 36.6 90 top
D1600  LMBR140FT1G  [SOD123H1_4]  128.19 70.01 180 top
D1700  LMBR140FT1G  [SOD123H1_4]  153.7 49.82 90 top
D1800  T-1N4148WA  [SOD123H1_4]  128.65 56.37 0 top
D2400  NC LMBR140FT1G  [SOD123H1_4]  147.45 81.07 180 top
D2800  WS30DF  [DFN1006-2-H0_55]  92 120.65 270 bottom
D2801  WS30DF  [DFN1006-2-H0_55]  85.7 120.65 270 bottom
D2802  WS30DF  [DFN1006-2-H0_55]  77.8 120.6 270 bottom
D2803  WS30DF  [DFN1006-2-H0_55]  70.95 120.6 270 bottom
D2900  D12V0X1B2LP-7B  [DFN1006-2-0_6X1_0H0_5]  14.8 95.24 90 bottom
D2901  D12V0X1B2LP-7B  [DFN1006-2-0_6X1_0H0_5]  14.72 92.78 270 bottom
D2902  D12V0X1B2LP-7B  [DFN1006-2-0_6X1_0H0_5]  14.7 85.17 90 bottom
D2903  D12V0X1B2LP-7B  [DFN1006-2-0_6X1_0H0_5]  14.64 82.89 270 bottom
D3000  D12V0X1B2LP-7B  [DFN1006-2-0_6X1_0H0_5]  14.45 70.48 90 bottom
D3001  D12V0X1B2LP-7B  [DFN1006-2-0_6X1_0H0_5]  14.5 67.92 270 bottom
D3002  D12V0X1B2LP-7B  [DFN1006-2-0_6X1_0H0_5]  15.07 60.5 90 bottom
D3003  D12V0X1B2LP-7B  [DFN1006-2-0_6X1_0H0_5]  15.01 57.95 270 bottom
D3400  ESDX56432E24-3/TR  [SOT23-H1_1]  133.12 123.65 0 bottom
D3401  ESDX56432E24-3/TR  [SOT23-H1_1]  124.92 123.66 0 bottom
D3402  ESDX56432E24-3/TR  [SOT23-H1_1]  117.34 123.66 0 bottom
D3403  ESDX56432E24-3/TR  [SOT23-H1_1]  110.1 123.65 0 bottom
D3600  LMBR140FT1G  [SOD123H1_4]  177.1 7.97 0 top
D3601  LMBR140FT1G  [SOD123H1_4]  162.74 7.97 0 top
D4000  RSES12V020R2  [ESD0402H0_35-RSES12V020R2]  164.08 123.52 180 top
D4001  RSES12V020R2  [ESD0402H0_35-RSES12V020R2]  167.14 123.57 0 top
F500  0501010.WRA  [FUSE-3_2X1_63H1_0]  125.7 32.6 180 bottom
F501  0501010.WRA  [FUSE-3_2X1_63H1_0]  125.9 28.65 180 bottom
HOLE3600  -  [HOLE-C5_0D2_2]  38 5 0 top
